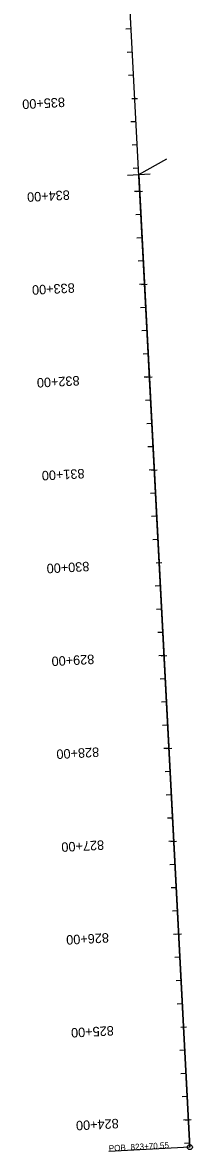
# Model space of a CAD drawing. Extents: x 2280195 to 2281869, y 391521 to 396826.
# Drawn here: x 2281686 to 2281869, y 391521 to 392735 of the extents above; entities that cross this region are included whole.
import ezdxf

# ---------------------------------------------------------------- set-up
doc = ezdxf.new("R2010")
doc.units = 0
for name, color, linetype in [('Default', 7, 'Continuous'), ('oleExistingMitigation', 7, 'Continuous'), ('oleFarmland', 7, 'Continuous'), ('olePrairies', 7, 'Continuous'), ('oleWildlife', 7, 'Continuous')]:
    doc.layers.add(name, color=color, linetype=linetype)

msp = doc.modelspace()

# ---------------------------------------------------------------- linework, layer by layer
at = {"layer": 'Default'}
for p, q in [((2281811.1, 392571.8), (2281841.4, 392588.8)), ((2281798.9, 392571.2), (2281823.2, 392572.5))]:
    msp.add_line(p, q, dxfattribs=at)
at = {"layer": 'oleExistingMitigation'}
msp.add_line((2281866, 391525.7), (2281779.1, 391521.1), dxfattribs=at)
msp.add_circle((2281866, 391525.7), 2.67, dxfattribs=at)
at = {"layer": 'oleFarmland'}
for p, q in [((2281803.7, 392653.4), (2281809.8, 392653.7)), ((2281812, 392553.7), (2281806.6, 392553.4)), ((2281817.3, 392453.9), (2281811.8, 392453.6)), ((2281822.5, 392354), (2281817, 392353.7)), ((2281827.7, 392254.1), (2281822.3, 392253.8)), ((2281829.9, 392154.1), (2281836, 392154.4)), ((2281838.2, 392054.4), (2281832.8, 392054.1)), ((2281843.5, 391954.5), (2281838, 391954.3)), ((2281848.7, 391854.7), (2281843.3, 391854.4)), ((2281854, 391754.8), (2281848.5, 391754.5)), ((2281856.2, 391654.8), (2281862.3, 391655.1)), ((2281864.5, 391555.1), (2281859, 391554.8))]:
    msp.add_line(p, q, dxfattribs=at)
at = {"layer": 'olePrairies'}
for p, q in [((2281802.8, 392728.5), (2281797.4, 392728.2)), ((2281804.1, 392703.5), (2281798.7, 392703.2)), ((2281805.5, 392678.5), (2281800, 392678.3)), ((2281803.7, 392653.4), (2281809.8, 392653.7)), ((2281808.1, 392628.6), (2281802.6, 392628.3)), ((2281809.4, 392603.7), (2281803.9, 392603.4)), ((2281810.7, 392578.7), (2281805.2, 392578.4)), ((2281809, 392553.6), (2281815.1, 392553.9)), ((2281813.3, 392528.8), (2281807.9, 392528.5)), ((2281814.6, 392503.8), (2281809.2, 392503.5)), ((2281815.9, 392478.8), (2281810.5, 392478.5)), ((2281814.2, 392453.7), (2281820.3, 392454)), ((2281818.6, 392428.9), (2281813.1, 392428.6)), ((2281819.9, 392403.9), (2281814.4, 392403.6)), ((2281821.2, 392379), (2281815.7, 392378.7)), ((2281819.4, 392353.8), (2281825.6, 392354.2)), ((2281823.8, 392329), (2281818.4, 392328.7)), ((2281825.1, 392304.1), (2281819.7, 392303.8)), ((2281826.4, 392279.1), (2281821, 392278.8)), ((2281824.7, 392254), (2281830.8, 392254.3)), ((2281829.1, 392229.2), (2281823.6, 392228.9)), ((2281830.4, 392204.2), (2281824.9, 392203.9)), ((2281831.7, 392179.2), (2281826.2, 392179)), ((2281829.9, 392154.1), (2281836, 392154.4)), ((2281834.3, 392129.3), (2281828.8, 392129)), ((2281835.6, 392104.3), (2281830.2, 392104.1)), ((2281836.9, 392079.4), (2281831.5, 392079.1)), ((2281835.2, 392054.2), (2281841.3, 392054.6)), ((2281839.5, 392029.4), (2281834.1, 392029.2)), ((2281840.9, 392004.5), (2281835.4, 392004.2)), ((2281842.2, 391979.5), (2281836.7, 391979.2)), ((2281840.4, 391954.4), (2281846.5, 391954.7)), ((2281844.8, 391929.6), (2281839.3, 391929.3)), ((2281846.1, 391904.6), (2281840.6, 391904.3)), ((2281847.4, 391879.6), (2281842, 391879.4)), ((2281845.7, 391854.5), (2281851.8, 391854.8)), ((2281850, 391829.7), (2281844.6, 391829.4)), ((2281851.3, 391804.8), (2281845.9, 391804.5)), ((2281852.7, 391779.8), (2281847.2, 391779.5)), ((2281850.9, 391754.7), (2281857, 391755)), ((2281855.3, 391729.9), (2281849.8, 391729.6)), ((2281856.6, 391704.9), (2281851.1, 391704.6)), ((2281857.9, 391679.9), (2281852.4, 391679.6)), ((2281856.2, 391654.8), (2281862.3, 391655.1)), ((2281860.5, 391630), (2281855.1, 391629.7)), ((2281861.8, 391605), (2281856.4, 391604.7)), ((2281863.1, 391580.1), (2281857.7, 391579.8)), ((2281861.4, 391554.9), (2281867.5, 391555.3)), ((2281865.8, 391530.1), (2281860.3, 391529.8))]:
    msp.add_line(p, q, dxfattribs=at)
at = {"layer": 'oleWildlife'}
for p, q in [((2281866, 391525.7), (2281801.4, 392754.8)), ((2281811.1, 392571.8), (2281866, 391525.7))]:
    msp.add_line(p, q, dxfattribs=at)

# ---------------------------------------------------------------- texts
at = {"layer": 'oleExistingMitigation'}
for s, p in [('POB ', (2281779.1, 391521.2)), ('823+70.55', (2281802.5, 391522.5))]:
    msp.add_text(s, height=6.48, rotation=3.0064, dxfattribs=at).set_placement(p)
at = {"layer": 'oleFarmland'}
for s, p in [('835+00', (2281731.6, 392654.7)), ('830+00', (2281757.8, 392155.4)), ('825+00', (2281784, 391656.1))]:
    msp.add_text(s, height=10.2, rotation=183.0064, dxfattribs=at).set_placement(p)
at = {"layer": 'olePrairies'}
for s, p in [('835+00', (2281731.6, 392654.7)), ('834+00', (2281736.8, 392554.9)), ('833+00', (2281742.1, 392455)), ('832+00', (2281747.3, 392355.2)), ('831+00', (2281752.6, 392255.3)), ('830+00', (2281757.8, 392155.4)), ('829+00', (2281763.1, 392055.6)), ('828+00', (2281768.3, 391955.7)), ('827+00', (2281773.6, 391855.8)), ('826+00', (2281778.8, 391756)), ('825+00', (2281784, 391656.1)), ('824+00', (2281789.3, 391556.3))]:
    msp.add_text(s, height=10.2, rotation=183.0064, dxfattribs=at).set_placement(p)

doc.saveas('drawing.dxf')
